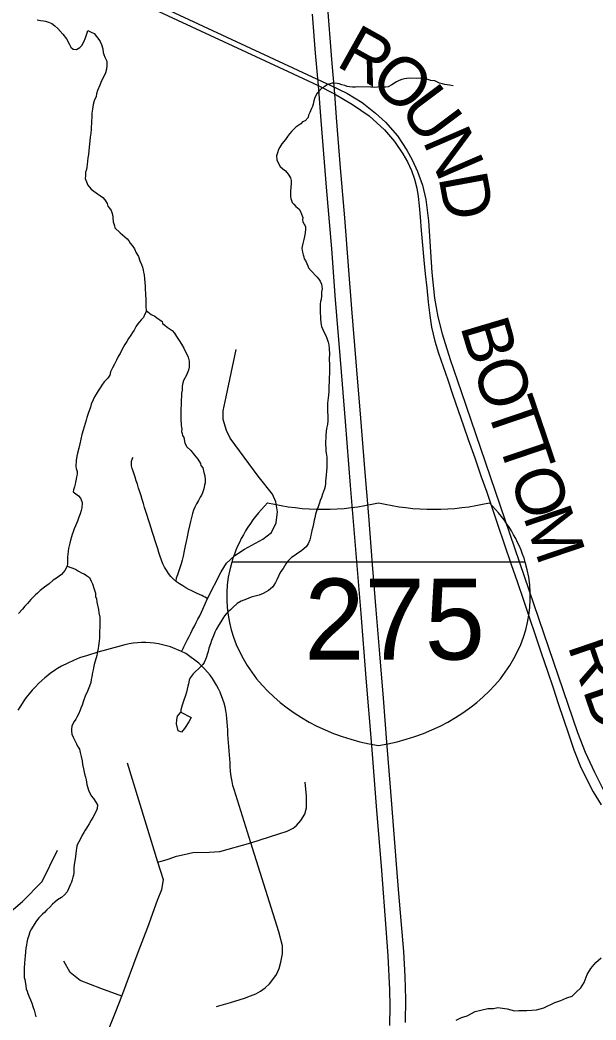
# Model space of a CAD drawing. Extents: x 44.2 to 78.2, y 4.5 to 26.5.
# Drawn here: x 50.4 to 51.074, y 19.388 to 20.558 of the extents above; entities that cross this region are included whole.
import ezdxf

# ---------------------------------------------------------------- set-up
doc = ezdxf.new("R2010")
doc.units = 0
for name, color, linetype in [('GM_X_County_Road', 7, 'Continuous'), ('GM_X_County_Road_Text', 7, 'Continuous'), ('GM_X_Interstate_Location', 7, 'Continuous'), ('GM_X_Interstate_Route', 7, 'Continuous'), ('GM_X_Interstate_Shield', 7, 'Continuous'), ('GM_X_Minor_Lake', 7, 'Continuous'), ('GM_X_Minor_River', 7, 'Continuous'), ('GM_X_Rail_Line', 7, 'Continuous'), ('GM_X_Township_Road', 7, 'Continuous')]:
    doc.layers.add(name, color=color, linetype=linetype)

msp = doc.modelspace()

# ---------------------------------------------------------------- linework, layer by layer
at = {"layer": 'GM_X_County_Road'}
msp.add_lwpolyline([(50.3952, 20.6454), (50.7135, 20.4974), (50.7487, 20.481), (50.7676, 20.4712), (50.7887, 20.4588), (50.8082, 20.4454), (50.8261, 20.4292), (50.8381, 20.4153), (50.8477, 20.4011), (50.853, 20.3915), (50.8577, 20.3816), (50.8615, 20.3715), (50.8642, 20.3607), (50.8658, 20.3512), (50.8669, 20.3401), (50.8679, 20.3268), (50.8691, 20.3113), (50.8707, 20.294), (50.8724, 20.2766), (50.874, 20.2604), (50.8757, 20.244), (50.8774, 20.2275), (50.8792, 20.212), (50.8814, 20.198), (50.8852, 20.1819), (50.8895, 20.1678), (50.8949, 20.1521), (50.9003, 20.1364), (50.906, 20.1196), (50.9126, 20.1008), (50.9188, 20.0827), (50.9242, 20.0669), (50.9318, 20.0452), (50.9391, 20.0243), (50.9458, 20.0052), (50.9522, 19.9863), (50.9588, 19.9666), (50.9661, 19.9448), (50.9745, 19.9205), (50.9815, 19.9006), (50.9888, 19.8788), (50.9959, 19.8579), (51.0026, 19.8382), (51.0095, 19.817), (51.0171, 19.7956), (51.0234, 19.7764), (51.0296, 19.7579), (51.0358, 19.7397), (51.0419, 19.7213), (51.0479, 19.7037), (51.055, 19.685), (51.0624, 19.6699), (51.0704, 19.6547), (51.0797, 19.6392)], dxfattribs=at)
at = {"layer": 'GM_X_Interstate_Route'}
for points in [[(50.7593, 20.577), (50.7644, 20.5113), (50.7676, 20.4712), (50.7699, 20.4434), (50.7746, 20.3844), (50.7793, 20.3261), (50.7837, 20.27), (50.7876, 20.2197), (50.7929, 20.1576), (50.7982, 20.0918), (50.803, 20.0329), (50.8075, 19.9773), (50.812, 19.9204), (50.8163, 19.8675), (50.8205, 19.816), (50.8246, 19.7642), (50.8287, 19.7125), (50.8328, 19.6598), (50.8365, 19.6152), (50.8395, 19.575), (50.8424, 19.5401), (50.8459, 19.4993), (50.8483, 19.4677), (50.8501, 19.4386), (50.8508, 19.4119), (50.8504, 19.3846)], [(50.7418, 20.5642), (50.7453, 20.5188), (50.7487, 20.481), (50.7519, 20.4399), (50.7581, 20.3621), (50.7643, 20.29), (50.7687, 20.2301), (50.7749, 20.1558), (50.7803, 20.0878), (50.7863, 20.0129), (50.7923, 19.9379), (50.7986, 19.8631), (50.8045, 19.7876), (50.811, 19.7086), (50.8164, 19.6376), (50.8226, 19.5625), (50.8278, 19.4948), (50.8301, 19.4627), (50.8322, 19.423), (50.8327, 19.4043), (50.8323, 19.3811)]]:
    msp.add_lwpolyline(points, dxfattribs=at)
at = {"layer": 'GM_X_Interstate_Shield'}
msp.add_line((50.9909, 19.9232), (50.6476, 19.9232), dxfattribs=at)
msp.add_line((50.9909, 19.9232), (50.6476, 19.9232), dxfattribs=at)
for centre, start_param, end_param in [((50.8636, 19.8826), 2.47259, 2.911027), ((50.7544, 20.1626), 4.415841, 5.008937), ((50.8841, 20.1626), 4.415841, 5.008937), ((50.7749, 19.8826), 0.230566, 0.669003), ((50.8636, 19.8826), 2.911027, 4.511031), ((50.7749, 19.8826), 4.913747, 6.513751)]:
    msp.add_ellipse(centre, major_axis=(0.2219, 0), ratio=0.8, start_param=start_param, end_param=end_param, dxfattribs=at)
at = {"layer": 'GM_X_Minor_Lake'}
for points in [[(50.5879, 19.7477), (50.6, 19.7416), (50.5972, 19.7364), (50.5925, 19.7285), (50.589, 19.7244), (50.5849, 19.726), (50.5828, 19.734), (50.5832, 19.7389)], [(50.5832, 19.7389), (50.5842, 19.743), (50.5879, 19.7477)]]:
    msp.add_lwpolyline(points, dxfattribs=at)
at = {"layer": 'GM_X_Minor_River'}
for points in [[(50.4201, 20.5577), (50.4238, 20.5569), (50.4273, 20.5564), (50.4299, 20.5563), (50.4333, 20.5551), (50.4371, 20.5535), (50.4408, 20.5507), (50.4441, 20.5476), (50.45, 20.541), (50.4541, 20.5356), (50.4573, 20.5298), (50.4595, 20.5259), (50.4621, 20.5236), (50.4659, 20.5231), (50.4698, 20.5253), (50.4721, 20.5279), (50.4745, 20.532), (50.4765, 20.5365), (50.4777, 20.5403), (50.4786, 20.5425), (50.4794, 20.5452), (50.4831, 20.5435), (50.4865, 20.5416), (50.4895, 20.5381), (50.492, 20.5346), (50.4935, 20.5323), (50.4953, 20.5288), (50.4967, 20.5238), (50.497, 20.5197), (50.498, 20.517), (50.4991, 20.5139), (50.5013, 20.5093), (50.5015, 20.5044), (50.501, 20.5002), (50.4998, 20.4957), (50.4981, 20.4916), (50.4954, 20.4863), (50.4933, 20.4814), (50.4905, 20.4751), (50.4893, 20.4713), (50.4888, 20.4679), (50.4868, 20.463), (50.4855, 20.4585), (50.4846, 20.4532), (50.4841, 20.4487), (50.484, 20.4437), (50.4835, 20.4392), (50.4833, 20.4297), (50.4828, 20.4252), (50.4819, 20.4203), (50.4804, 20.4044), (50.4799, 20.4002), (50.4794, 20.3964), (50.4789, 20.3923), (50.4784, 20.3885), (50.478, 20.3855), (50.4775, 20.3828), (50.4767, 20.3794), (50.4766, 20.3753), (50.4761, 20.3722), (50.4793, 20.3642), (50.483, 20.3595), (50.4905, 20.354), (50.4942, 20.3517), (50.4968, 20.3497), (50.499, 20.347), (50.502, 20.3427), (50.5026, 20.3397), (50.5045, 20.3373), (50.5067, 20.3346), (50.5081, 20.33), (50.5084, 20.3266), (50.509, 20.3213), (50.5104, 20.3167), (50.5107, 20.3144), (50.517, 20.3086), (50.5226, 20.3039), (50.5252, 20.3015), (50.5271, 20.2992), (50.5289, 20.2965), (50.5311, 20.2938), (50.5337, 20.2899)], [(50.9066, 20.4805), (50.9024, 20.4814), (50.8994, 20.4818), (50.8967, 20.4819), (50.8941, 20.4827), (50.8907, 20.4836), (50.8873, 20.4852), (50.8851, 20.4864), (50.8805, 20.4869), (50.8722, 20.4894), (50.8684, 20.4895), (50.8642, 20.4892), (50.8559, 20.4894), (50.8525, 20.4891), (50.8498, 20.4888), (50.8467, 20.4881), (50.8433, 20.4867), (50.8402, 20.4853), (50.8348, 20.4816), (50.8306, 20.4794), (50.8275, 20.4788), (50.823, 20.4789), (50.8207, 20.4793), (50.818, 20.479), (50.815, 20.4787), (50.8127, 20.4788), (50.8104, 20.4788), (50.7949, 20.4792), (50.7922, 20.4789), (50.7888, 20.479), (50.7854, 20.4795), (50.7827, 20.4799), (50.7797, 20.4808), (50.7763, 20.4816), (50.7733, 20.4828), (50.771, 20.4833), (50.7672, 20.4838), (50.765, 20.4838), (50.7627, 20.4827), (50.7596, 20.4821), (50.7565, 20.4799), (50.753, 20.4777), (50.7503, 20.4751), (50.7476, 20.4721), (50.746, 20.4691), (50.7444, 20.4658), (50.7436, 20.4631), (50.7427, 20.459), (50.7419, 20.4563), (50.741, 20.4541), (50.739, 20.4492), (50.7374, 20.4462), (50.737, 20.4436), (50.7335, 20.4395), (50.7304, 20.4384), (50.7284, 20.4362), (50.7226, 20.4322), (50.718, 20.4274), (50.7152, 20.4244), (50.7129, 20.4214), (50.7105, 20.4177), (50.7062, 20.4125), (50.7038, 20.4088), (50.7022, 20.4062), (50.701, 20.402), (50.7001, 20.3986), (50.7004, 20.3941), (50.7018, 20.3906), (50.7044, 20.386), (50.7073, 20.3836), (50.7103, 20.3809), (50.7136, 20.377), (50.7162, 20.3728), (50.7169, 20.3697), (50.7172, 20.3663), (50.7167, 20.3618), (50.7162, 20.3568), (50.7165, 20.3542), (50.7164, 20.3512), (50.7167, 20.3489), (50.7174, 20.3462), (50.7181, 20.3439), (50.7203, 20.3419), (50.7225, 20.3392), (50.7263, 20.3361), (50.7281, 20.3334), (50.7292, 20.3303), (50.7306, 20.3265), (50.7305, 20.3238), (50.7308, 20.3216), (50.7323, 20.3185), (50.7337, 20.3158), (50.734, 20.3128), (50.7335, 20.3086), (50.7327, 20.3044), (50.7318, 20.3007), (50.7306, 20.2961), (50.7301, 20.2927), (50.7297, 20.2905), (50.7303, 20.2859), (50.731, 20.2829)], [(50.5337, 20.2899), (50.5358, 20.2853), (50.5384, 20.2807), (50.5401, 20.2757), (50.5419, 20.2715), (50.543, 20.2684), (50.544, 20.265), (50.5444, 20.2627), (50.545, 20.2593), (50.5457, 20.2547), (50.5462, 20.2463), (50.5465, 20.2418), (50.5468, 20.238), (50.5467, 20.2357), (50.547, 20.2315), (50.5469, 20.2285), (50.5472, 20.2247), (50.5471, 20.2213), (50.5474, 20.219), (50.5474, 20.2163), (50.5454, 20.2126), (50.5445, 20.2096), (50.5418, 20.2066), (50.5379, 20.2022), (50.5359, 20.1992), (50.5335, 20.1947), (50.5316, 20.1921), (50.5296, 20.1887), (50.5268, 20.185), (50.5248, 20.1816), (50.5225, 20.1779), (50.5209, 20.1753), (50.5185, 20.1708), (50.5169, 20.1674), (50.5149, 20.1637), (50.5129, 20.1596), (50.5105, 20.1547), (50.5081, 20.1506), (50.5057, 20.1461), (50.5048, 20.1419), (50.5025, 20.1386), (50.4982, 20.1342), (50.4958, 20.1304), (50.4938, 20.1271), (50.4915, 20.1237), (50.4891, 20.1196), (50.4871, 20.1166), (50.4855, 20.1132), (50.4831, 20.108), (50.4822, 20.1046), (50.4798, 20.0971), (50.4781, 20.0926), (50.4773, 20.0892), (50.476, 20.0854), (50.4748, 20.0816), (50.4736, 20.0775), (50.4723, 20.0726), (50.471, 20.0673), (50.4697, 20.0617), (50.4689, 20.0568), (50.4672, 20.0507), (50.4663, 20.0473), (50.4655, 20.0421), (50.4653, 20.0352), (50.4656, 20.0329), (50.4666, 20.0295), (50.4666, 20.0261), (50.4661, 20.0231), (50.4657, 20.0204), (50.4648, 20.017), (50.4644, 20.0144), (50.4635, 20.0114), (50.4623, 20.008), (50.4622, 20.0057), (50.4682, 20.001), (50.4708, 19.9983), (50.4722, 19.9944), (50.4725, 19.9922), (50.4724, 19.9869), (50.4716, 19.9835), (50.4703, 19.9797), (50.4687, 19.9759), (50.4671, 19.9711), (50.465, 19.9658), (50.4634, 19.9621), (50.4622, 19.9587), (50.461, 19.9557), (50.4601, 19.953), (50.4589, 19.9489), (50.4581, 19.9455), (50.4576, 19.9425), (50.4568, 19.9391), (50.4563, 19.9361), (50.4558, 19.9323), (50.4554, 19.93), (50.4553, 19.9274), (50.4556, 19.9243), (50.4556, 19.9217), (50.4551, 19.9186), (50.4523, 19.9134), (50.4484, 19.9089)], [(50.731, 20.2829), (50.7321, 20.2806), (50.7324, 20.2783), (50.7339, 20.276), (50.7353, 20.2725), (50.7364, 20.2698), (50.7374, 20.2675), (50.7404, 20.264), (50.747, 20.257), (50.7493, 20.2543), (50.7511, 20.252), (50.7525, 20.2485), (50.7528, 20.2462), (50.7532, 20.2432), (50.7527, 20.2394), (50.7526, 20.2349), (50.7521, 20.2307), (50.7516, 20.2281), (50.7512, 20.225), (50.751, 20.2171), (50.7515, 20.208), (50.7518, 20.2038), (50.7521, 20.2011), (50.7524, 20.1988), (50.7542, 20.1954), (50.7556, 20.1919), (50.7575, 20.1885), (50.7589, 20.1854), (50.7603, 20.1808), (50.761, 20.1774), (50.7616, 20.1728), (50.7619, 20.1671), (50.7617, 20.161), (50.7619, 20.1538), (50.7621, 20.1458), (50.7615, 20.1375), (50.7614, 20.1333), (50.7613, 20.1299), (50.7611, 20.1231), (50.7606, 20.1186), (50.7596, 20.1091), (50.7594, 20.1019), (50.7597, 20.0992), (50.76, 20.0947), (50.7599, 20.0886), (50.7594, 20.0844), (50.7585, 20.0795), (50.758, 20.0761), (50.7575, 20.072), (50.7573, 20.061), (50.7575, 20.0568), (50.7578, 20.0534), (50.7581, 20.0507), (50.7588, 20.0461), (50.7587, 20.042), (50.759, 20.0382), (50.7588, 20.034), (50.7584, 20.0298), (50.7582, 20.0249), (50.7573, 20.0181), (50.7572, 20.0151), (50.7568, 20.0117), (50.7559, 20.009), (50.7551, 20.006), (50.7539, 20.0026), (50.7526, 19.9989), (50.751, 19.9955), (50.7502, 19.9925), (50.7486, 19.988), (50.7474, 19.9854), (50.7457, 19.9793), (50.7448, 19.9752), (50.744, 19.9725), (50.7431, 19.968), (50.7423, 19.9642), (50.7414, 19.9601), (50.741, 19.9578), (50.7401, 19.9548), (50.7397, 19.9525), (50.7388, 19.9492), (50.7368, 19.9447), (50.7345, 19.9413), (50.7294, 19.9369), (50.7232, 19.9325), (50.7205, 19.9307), (50.7174, 19.9285), (50.7131, 19.9244), (50.7108, 19.9214), (50.7092, 19.9184), (50.7076, 19.9158), (50.7052, 19.9125), (50.704, 19.9102), (50.7024, 19.9069), (50.7004, 19.9027), (50.6988, 19.8994), (50.6969, 19.8964), (50.6953, 19.8941), (50.6929, 19.8919), (50.6906, 19.8901), (50.6844, 19.8865), (50.6798, 19.8847)], [(50.5474, 20.2177), (50.5534, 20.2128), (50.5575, 20.2111), (50.5601, 20.2092), (50.5635, 20.2068), (50.5661, 20.2048), (50.5664, 20.2026), (50.5694, 20.2006), (50.572, 20.1982), (50.578, 20.1943), (50.5805, 20.1912), (50.5831, 20.1873), (50.586, 20.1827), (50.5889, 20.1784), (50.5915, 20.1738), (50.5965, 20.1631), (50.5976, 20.1585), (50.5978, 20.1547), (50.5977, 20.1513), (50.5969, 20.1479), (50.5945, 20.1419), (50.5913, 20.1359), (50.5904, 20.1329), (50.5896, 20.1291), (50.5895, 20.1246), (50.589, 20.1208), (50.5889, 20.117), (50.5884, 20.1132), (50.588, 20.0969), (50.5882, 20.0912), (50.5884, 20.0832), (50.5891, 20.079), (50.589, 20.076), (50.5897, 20.0737), (50.59, 20.0714), (50.5915, 20.0691), (50.5928, 20.0626), (50.595, 20.058), (50.5998, 20.0537), (50.6042, 20.0483), (50.6079, 20.0436), (50.6112, 20.0386), (50.6115, 20.0363), (50.6137, 20.0336), (50.6151, 20.0283), (50.6162, 20.0241), (50.6164, 20.0191), (50.6163, 20.0161), (50.6159, 20.0135), (50.615, 20.0089), (50.6142, 20.0067), (50.6134, 20.0044), (50.6122, 20.0018), (50.6106, 19.9992), (50.6086, 19.9954), (50.6062, 19.9913), (50.6046, 19.9876), (50.603, 19.9842), (50.6017, 19.9801), (50.5992, 19.971), (50.5983, 19.9657), (50.5967, 19.9593), (50.5954, 19.9529), (50.5941, 19.9473), (50.5932, 19.9423), (50.5919, 19.9363), (50.5906, 19.9303), (50.5897, 19.9257), (50.5885, 19.9212), (50.5864, 19.9156), (50.584, 19.9084), (50.5827, 19.9047), (50.5823, 19.9013)], [(50.4551, 19.9186), (50.4649, 19.915), (50.4682, 19.9126), (50.4727, 19.9102), (50.475, 19.9094), (50.4776, 19.9078), (50.481, 19.9054), (50.4831, 19.9012), (50.4846, 19.8978), (50.4867, 19.8916), (50.4881, 19.887), (50.4884, 19.8829), (50.4894, 19.8802), (50.4897, 19.8764), (50.4918, 19.868), (50.4921, 19.8638), (50.4931, 19.8588), (50.4934, 19.855), (50.4928, 19.8346), (50.4924, 19.8308), (50.4918, 19.8255), (50.4914, 19.8221), (50.4905, 19.8187), (50.4897, 19.8142), (50.4867, 19.8036), (50.4859, 19.7998), (50.4854, 19.7972), (50.4846, 19.7942), (50.4845, 19.7919), (50.4841, 19.7889), (50.4832, 19.7859), (50.4828, 19.7825), (50.4811, 19.778), (50.4787, 19.7723), (50.4763, 19.7663), (50.4743, 19.7611), (50.4726, 19.7558), (50.471, 19.7524), (50.4702, 19.7502), (50.4685, 19.7453), (50.4662, 19.7419), (50.4654, 19.7397), (50.4634, 19.7367), (50.4618, 19.7341), (50.4606, 19.7314), (50.4601, 19.728), (50.4601, 19.7254), (50.4607, 19.722), (50.4622, 19.7185), (50.4647, 19.7131), (50.4661, 19.7108), (50.4672, 19.7081), (50.4694, 19.7043), (50.4704, 19.7005), (50.4715, 19.6959), (50.4725, 19.6909), (50.4731, 19.6867), (50.4741, 19.6814), (50.4755, 19.6757), (50.4765, 19.6718), (50.4772, 19.6684), (50.4775, 19.6657), (50.4782, 19.6631), (50.4793, 19.6592), (50.48, 19.6566), (50.4832, 19.6497), (50.4858, 19.6466), (50.4887, 19.6423), (50.4905, 19.6392), (50.49, 19.6351), (50.4892, 19.6328), (50.4852, 19.6246), (50.4832, 19.6212), (50.4809, 19.6171), (50.4789, 19.6141), (50.4777, 19.6119), (50.4761, 19.6096), (50.4745, 19.607), (50.4725, 19.604), (50.4709, 19.6003), (50.4689, 19.5962), (50.4673, 19.5932), (50.4665, 19.5909), (50.4661, 19.5883), (50.4656, 19.586), (50.4652, 19.5822), (50.4647, 19.5788), (50.4646, 19.5762), (50.4638, 19.572), (50.4633, 19.569), (50.4628, 19.5656), (50.4628, 19.5633), (50.4627, 19.5599), (50.4626, 19.5572), (50.4618, 19.5546), (50.461, 19.5516), (50.4601, 19.549), (50.4589, 19.5467)], [(50.4484, 19.9089), (50.4457, 19.9067), (50.4426, 19.9045), (50.4387, 19.902), (50.4341, 19.8979), (50.4286, 19.8939), (50.4236, 19.8899), (50.4205, 19.8869), (50.4182, 19.8851), (50.4154, 19.8821), (50.4127, 19.8795), (50.4107, 19.8773), (50.4088, 19.8747), (50.4057, 19.8717), (50.4029, 19.8684), (50.3982, 19.8632)], [(50.6798, 19.8847), (50.6703, 19.8823), (50.6649, 19.8798), (50.6588, 19.8776), (50.6538, 19.8747), (50.6491, 19.8707), (50.646, 19.8674), (50.6433, 19.8651), (50.6409, 19.8626), (50.6393, 19.8603), (50.637, 19.8573), (50.635, 19.8536), (50.6322, 19.8491), (50.6294, 19.8443), (50.6278, 19.8413), (50.6262, 19.8371), (50.625, 19.8345), (50.6238, 19.8315), (50.6226, 19.8277), (50.6209, 19.8225), (50.6201, 19.8187), (50.6188, 19.8153), (50.618, 19.8123), (50.6168, 19.8093), (50.6152, 19.8059), (50.6136, 19.8037), (50.6113, 19.8011), (50.6023, 19.7926), (50.5991, 19.7881), (50.5979, 19.7851), (50.5971, 19.781), (50.5962, 19.778), (50.5945, 19.7712), (50.5933, 19.7674), (50.592, 19.7629), (50.5896, 19.7561), (50.5888, 19.7531), (50.5879, 19.7505), (50.5879, 19.7477)], [(50.4589, 19.5467), (50.4565, 19.5411), (50.4549, 19.5377), (50.4518, 19.534), (50.4483, 19.5311), (50.4436, 19.5281), (50.4405, 19.5256), (50.4378, 19.523), (50.4347, 19.5197), (50.4312, 19.5163), (50.4285, 19.5134), (50.4261, 19.5115), (50.4218, 19.5071), (50.4191, 19.5037), (50.4163, 19.4993), (50.4132, 19.4944), (50.4115, 19.4907), (50.4103, 19.4865), (50.4087, 19.482), (50.4078, 19.4782), (50.4074, 19.4752), (50.4069, 19.4718), (50.4059, 19.4627), (50.4054, 19.4586), (50.4053, 19.454), (50.4048, 19.4483), (50.4046, 19.4434), (50.4049, 19.44), (50.4049, 19.4373), (50.4056, 19.435), (50.4069, 19.4274), (50.4072, 19.424), (50.4083, 19.4213), (50.409, 19.4186), (50.4108, 19.4148), (50.4122, 19.4113), (50.4136, 19.4071), (50.4154, 19.4022), (50.4164, 19.3991), (50.4185, 19.3911)], [(50.9101, 19.3875), (50.9162, 19.3905), (50.9231, 19.3923), (50.9323, 19.3974), (50.9391, 19.3992), (50.9471, 19.401), (50.9536, 19.4012), (50.9589, 19.4023), (50.9642, 19.4014), (50.9699, 19.4006), (50.9782, 19.3985), (50.9835, 19.3988), (50.9926, 19.3987), (50.9987, 19.3989), (51.004, 19.3996), (51.0127, 19.4017), (51.0254, 19.408), (51.0326, 19.4105), (51.0395, 19.4134), (51.0456, 19.4156), (51.0506, 19.4201), (51.056, 19.4253), (51.0599, 19.4313), (51.0635, 19.4408), (51.0678, 19.4479), (51.0736, 19.455), (51.0798, 19.4603)]]:
    msp.add_lwpolyline(points, dxfattribs=at)
at = {"layer": 'GM_X_Rail_Line'}
msp.add_lwpolyline([(50.3927, 20.6536), (50.7634, 20.4811), (50.7821, 20.4719), (50.8, 20.4609), (50.8159, 20.4487), (50.8276, 20.4379), (50.8414, 20.422), (50.8522, 20.4053), (50.8588, 20.3939), (50.8649, 20.3802), (50.8706, 20.3643), (50.8746, 20.3476), (50.8777, 20.3225), (50.8818, 20.262), (50.8848, 20.2321), (50.8887, 20.2104), (50.8936, 20.1904), (50.9031, 20.1605), (50.9158, 20.123), (51.052, 19.7238), (51.0609, 19.7009), (51.0718, 19.6774), (51.0821, 19.6574)], dxfattribs=at)
at = {"layer": 'GM_X_Township_Road'}
for points in [[(50.5888, 19.8188), (50.5893, 19.8197), (50.5898, 19.8207), (50.5906, 19.8222), (50.5917, 19.8243), (50.5929, 19.8267), (50.5944, 19.8296), (50.596, 19.8328), (50.5978, 19.8364), (50.5997, 19.8402), (50.6018, 19.8443), (50.6039, 19.8484), (50.606, 19.8525), (50.6081, 19.8566), (50.6102, 19.8606), (50.6121, 19.8646), (50.6139, 19.8682), (50.6193, 19.8808), (50.6354, 19.9121), (50.6413, 19.9221), (50.6512, 19.9309), (50.6625, 19.9384), (50.6841, 19.9501), (50.694, 19.9578), (50.6997, 19.9692), (50.7011, 19.9823), (50.699, 19.9939), (50.6951, 20.0028), (50.6784, 20.024), (50.6459, 20.0682), (50.6413, 20.0774), (50.6376, 20.0902), (50.6377, 20.1001), (50.6409, 20.1167), (50.6526, 20.1719)], [(50.6188, 19.881), (50.6182, 19.8813), (50.6166, 19.8821), (50.6147, 19.883), (50.6125, 19.8842), (50.61, 19.8854), (50.6072, 19.8867), (50.6041, 19.8882), (50.6008, 19.8897), (50.5974, 19.8914), (50.5939, 19.8933), (50.5903, 19.8954), (50.5866, 19.8978), (50.583, 19.9004), (50.5796, 19.9033), (50.5765, 19.9066), (50.5737, 19.91), (50.5712, 19.9137), (50.569, 19.9174), (50.567, 19.9214), (50.5654, 19.9256), (50.5639, 19.93), (50.5624, 19.9344), (50.561, 19.9389), (50.5595, 19.9436), (50.558, 19.9483), (50.5565, 19.9531), (50.5549, 19.958), (50.5533, 19.9629), (50.5517, 19.9679), (50.5502, 19.9729), (50.5486, 19.9778), (50.5471, 19.9826), (50.5457, 19.9873), (50.5444, 19.9919), (50.5429, 19.9964), (50.5415, 20.001), (50.5401, 20.0055), (50.5386, 20.0099), (50.5372, 20.0143), (50.5358, 20.0185), (50.5345, 20.0225), (50.5333, 20.0263), (50.5322, 20.0297), (50.5312, 20.0329), (50.5305, 20.0359), (50.5302, 20.0387), (50.5304, 20.0415), (50.5312, 20.0439), (50.5321, 20.0458)], [(50.6296, 19.4033), (50.6462, 19.4081), (50.6625, 19.413), (50.6697, 19.4157), (50.6758, 19.4183), (50.6813, 19.4214), (50.6865, 19.4251), (50.6918, 19.43), (50.6957, 19.4349), (50.6999, 19.441), (50.7029, 19.4477), (50.7052, 19.4553), (50.7068, 19.465), (50.7071, 19.4745), (50.7025, 19.4907), (50.6698, 19.595), (50.6503, 19.6572), (50.649, 19.6619), (50.6479, 19.6666), (50.6472, 19.6707), (50.6467, 19.6749), (50.6463, 19.6792), (50.6459, 19.6836), (50.6456, 19.6883), (50.6452, 19.693), (50.6449, 19.6978), (50.6446, 19.7026), (50.6442, 19.7074), (50.6438, 19.7122), (50.6435, 19.717), (50.6432, 19.7218), (50.6429, 19.7265), (50.6426, 19.7312), (50.6422, 19.7359), (50.6418, 19.7405), (50.6413, 19.7452), (50.6406, 19.7497), (50.6397, 19.7541), (50.6386, 19.7583), (50.6372, 19.7625), (50.6357, 19.7668), (50.6349, 19.7689), (50.634, 19.771), (50.632, 19.7752), (50.6299, 19.7794), (50.6276, 19.7834), (50.6251, 19.7873), (50.6223, 19.791), (50.6193, 19.7946), (50.616, 19.7982), (50.6125, 19.8017), (50.6089, 19.8051), (50.5937, 19.8162), (50.5888, 19.8188), (50.5761, 19.824), (50.5714, 19.8255), (50.5666, 19.8267), (50.5618, 19.8277), (50.5569, 19.8285), (50.552, 19.829), (50.5471, 19.8292), (50.5422, 19.8292), (50.5372, 19.829), (50.5323, 19.8285), (50.5275, 19.8277), (50.5226, 19.8267), (50.5012, 19.8205), (50.4909, 19.8179), (50.479, 19.8142), (50.4696, 19.8112), (50.4625, 19.8083), (50.4558, 19.8052), (50.4486, 19.8016), (50.4436, 19.7988), (50.4414, 19.7973), (50.4387, 19.7954), (50.4356, 19.7932), (50.4324, 19.7906), (50.4289, 19.7879), (50.4254, 19.7847), (50.4217, 19.7812), (50.418, 19.7775), (50.4142, 19.7734), (50.4105, 19.769), (50.4069, 19.7645), (50.4035, 19.7598), (50.4004, 19.7549), (50.3975, 19.7499)], [(50.2848, 19.2628), (50.3573, 19.2758), (50.3951, 19.2779), (50.4311, 19.2914), (50.4652, 19.3172), (50.4862, 19.3399), (50.4964, 19.3587), (50.5121, 19.3975), (50.5189, 19.4153), (50.538, 19.4668), (50.5494, 19.4963), (50.5609, 19.5278), (50.566, 19.5402), (50.5677, 19.5516), (50.5613, 19.5722), (50.5258, 19.6879)], [(50.5613, 19.5722), (50.5733, 19.5757), (50.583, 19.5791), (50.5918, 19.5812), (50.6021, 19.5837), (50.621, 19.5841), (50.6335, 19.5848), (50.6698, 19.595), (50.7027, 19.6054), (50.7123, 19.6086), (50.7193, 19.612), (50.7234, 19.6151), (50.7283, 19.6211), (50.733, 19.6284), (50.735, 19.6359), (50.7352, 19.6493), (50.7333, 19.666)], [(50.3293, 19.4853), (50.3586, 19.4941), (50.3869, 19.5126), (50.403, 19.5263), (50.4259, 19.5497), (50.4438, 19.5862)], [(50.5189, 19.4153), (50.4945, 19.4245), (50.4701, 19.4338), (50.4586, 19.4431), (50.4511, 19.4565)]]:
    msp.add_lwpolyline(points, dxfattribs=at)

# ---------------------------------------------------------------- texts
at = {"layer": 'GM_X_County_Road_Text'}
for s, height, rotation, p in [('R', 0.0568, 330.7949, (50.7682, 20.5045)), ('O', 0.0568, 319.4169, (50.8065, 20.4834)), ('U', 0.0568, 306.9005, (50.8422, 20.4533)), ('N', 0.0568, 293.3784, (50.8704, 20.4164)), ('D', 0.0568, 280.4769, (50.8893, 20.3737)), ('B', 0.0568, 286.5845, (50.9146, 20.1993)), ('O', 0.0568, 288.7462, (50.9287, 20.1523)), ('T', 0.0568, 288.748, (50.9447, 20.1049)), ('T', 0.0568, 288.744, (50.9584, 20.0647)), ('O', 0.0568, 288.7462, (50.972, 20.0245)), ('M', 0.0568, 288.7471, (50.9881, 19.9771)), ('RD', 0.05682, 288.8938, (51.0401, 19.8257))]:
    msp.add_text(s, height=height, rotation=rotation, dxfattribs=at).set_placement(p)
at = {"layer": 'GM_X_Interstate_Location'}
for s in ['-', '.', ',']:
    msp.add_text(s, height=0.000189, dxfattribs=at).set_placement((50.8192, 19.8565))
msp.add_text('275', height=0.000189, rotation=0, dxfattribs=at).set_placement((50.7614, 19.8173))
at = {"layer": 'GM_X_Interstate_Shield'}
msp.add_text('275', height=0.0947, dxfattribs=at).set_placement((50.7325, 19.8093))

doc.saveas('drawing.dxf')
